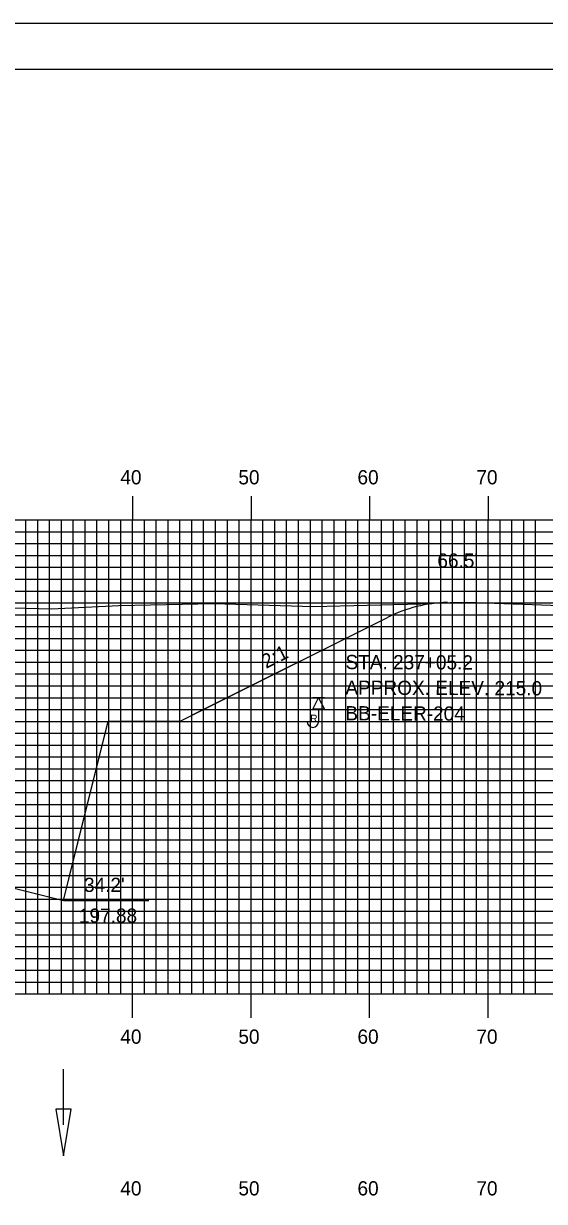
# Model space of a CAD drawing. Extents: x 1800749 to 1801092, y 442591 to 442811.
# Drawn here: x 1800945.4 to 1800989.3, y 442711.2 to 442810.5 of the extents above; entities that cross this region are included whole.
import ezdxf

# ---------------------------------------------------------------- set-up
doc = ezdxf.new("R2010")
doc.units = 0
for name, color, linetype in [('ANNOTATION', 7, 'Continuous'), ('BORDER', 7, 'Continuous'), ('BORING - REFUSAL', 7, 'Continuous'), ('D_Drainage_Ditch_Line', 7, 'Continuous'), ('D_Roadway_SlopeLines', 7, 'Continuous'), ('D_Text_Standard', 7, 'Continuous'), ('H_V ANNOTATION', 7, 'Continuous'), ('MAJOR', 7, 'Continuous'), ('MINOR', 7, 'Continuous'), ('PDRAIN', 7, 'Continuous'), ('PLOT BOUNDARY', 7, 'Continuous'), ('S_Roadway_Centerline', 7, 'Continuous')]:
    doc.layers.add(name, color=color, linetype=linetype)

msp = doc.modelspace()

# ---------------------------------------------------------------- linework, layer by layer
at = {"layer": 'ANNOTATION'}
for p, q in [((1800960.503, 442752.665), (1800976.044, 442760.436)), ((1800958.503, 442751.665), (1800960.503, 442752.665)), ((1800949.723, 442740.547), (1800952.503, 442751.665)), ((1800958.503, 442751.665), (1800952.503, 442751.665)), ((1800952.503, 442751.665), (1800958.503, 442751.665)), ((1800948.723, 442736.547), (1800949.723, 442740.547))]:
    msp.add_line(p, q, dxfattribs=at)
msp.add_arc((1800981.411, 442749.703), 12, 91.41331, 116.56505, dxfattribs=at)
at = {"layer": 'BORDER'}
msp.add_lwpolyline([(1800764.949, 442596.665), (1801084.949, 442596.665), (1801084.949, 442806.665), (1800764.949, 442806.665)], close=True, dxfattribs=at)
at = {"layer": 'BORING - REFUSAL'}
for p, q in [((1800970.729, 442753.665), (1800969.769, 442753.665)), ((1800970.249, 442752.706), (1800970.249, 442751.647))]:
    msp.add_line(p, q, dxfattribs=at)
msp.add_lwpolyline([(1800970.249, 442753.665), (1800970.729, 442752.706), (1800969.769, 442752.706)], close=True, dxfattribs=at)
msp.add_arc((1800969.764, 442751.647), 0.485, 180, 0, dxfattribs=at)
at = {"layer": 'D_Drainage_Ditch_Line'}
msp.add_line((1800948.724, 442717.626), (1800948.724, 442722.325), dxfattribs=at)
msp.add_lwpolyline([(1800949.38, 442718.939), (1800948.068, 442718.939), (1800948.724, 442715.002)], close=True, dxfattribs=at)
at = {"layer": 'D_Roadway_SlopeLines'}
for points in [[(1800948.723, 442736.547), (1800952.503, 442751.665), (1800958.503, 442751.665), (1800976.044, 442760.436)], [(1800934.549, 442740.091), (1800948.723, 442736.547)]]:
    msp.add_lwpolyline(points, dxfattribs=at)
at = {"layer": 'MAJOR'}
for p, q in [((1800954.549, 442770.669), (1800954.549, 442768.665)), ((1800964.549, 442770.669), (1800964.549, 442768.665)), ((1800974.549, 442770.669), (1800974.549, 442768.665)), ((1800984.549, 442770.669), (1800984.549, 442768.665)), ((1800774.549, 442768.665), (1801054.549, 442768.665)), ((1800774.549, 442768.665), (1801054.549, 442768.665)), ((1800954.549, 442728.665), (1800954.549, 442768.665)), ((1800964.549, 442728.665), (1800964.549, 442768.665)), ((1800974.549, 442728.665), (1800974.549, 442768.665)), ((1800984.549, 442728.665), (1800984.549, 442768.665)), ((1800774.549, 442763.665), (1801054.549, 442763.665)), ((1800774.549, 442758.665), (1801054.549, 442758.665)), ((1800774.549, 442753.665), (1801054.549, 442753.665)), ((1800774.549, 442748.665), (1801054.549, 442748.665)), ((1800774.549, 442743.665), (1801054.549, 442743.665)), ((1800774.549, 442738.665), (1801054.549, 442738.665)), ((1800774.549, 442733.665), (1801054.549, 442733.665)), ((1800774.549, 442728.665), (1801054.549, 442728.665)), ((1800774.549, 442728.665), (1801054.549, 442728.665)), ((1800954.549, 442726.661), (1800954.549, 442728.665)), ((1800964.549, 442726.661), (1800964.549, 442728.665)), ((1800974.549, 442726.661), (1800974.549, 442728.665)), ((1800984.549, 442726.661), (1800984.549, 442728.665))]:
    msp.add_line(p, q, dxfattribs=at)
at = {"layer": 'MINOR'}
for p, q in [((1800945.549, 442728.665), (1800945.549, 442768.665)), ((1800946.549, 442728.665), (1800946.549, 442768.665)), ((1800947.549, 442728.665), (1800947.549, 442768.665)), ((1800948.549, 442728.665), (1800948.549, 442768.665)), ((1800949.549, 442728.665), (1800949.549, 442768.665)), ((1800950.549, 442728.665), (1800950.549, 442768.665)), ((1800951.549, 442728.665), (1800951.549, 442768.665)), ((1800952.549, 442728.665), (1800952.549, 442768.665)), ((1800953.549, 442728.665), (1800953.549, 442768.665)), ((1800955.549, 442728.665), (1800955.549, 442768.665)), ((1800956.549, 442728.665), (1800956.549, 442768.665)), ((1800957.549, 442728.665), (1800957.549, 442768.665)), ((1800958.549, 442728.665), (1800958.549, 442768.665)), ((1800959.549, 442728.665), (1800959.549, 442768.665)), ((1800960.549, 442728.665), (1800960.549, 442768.665)), ((1800961.549, 442728.665), (1800961.549, 442768.665)), ((1800962.549, 442728.665), (1800962.549, 442768.665)), ((1800963.549, 442728.665), (1800963.549, 442768.665)), ((1800965.549, 442728.665), (1800965.549, 442768.665)), ((1800966.549, 442728.665), (1800966.549, 442768.665)), ((1800967.549, 442728.665), (1800967.549, 442768.665)), ((1800968.549, 442728.665), (1800968.549, 442768.665)), ((1800969.549, 442728.665), (1800969.549, 442768.665)), ((1800970.549, 442728.665), (1800970.549, 442768.665)), ((1800971.549, 442728.665), (1800971.549, 442768.665)), ((1800972.549, 442728.665), (1800972.549, 442768.665)), ((1800973.549, 442728.665), (1800973.549, 442768.665)), ((1800975.549, 442728.665), (1800975.549, 442768.665)), ((1800976.549, 442728.665), (1800976.549, 442768.665)), ((1800977.549, 442728.665), (1800977.549, 442768.665)), ((1800978.549, 442728.665), (1800978.549, 442768.665)), ((1800979.549, 442728.665), (1800979.549, 442768.665)), ((1800980.549, 442728.665), (1800980.549, 442768.665)), ((1800981.549, 442728.665), (1800981.549, 442768.665)), ((1800982.549, 442728.665), (1800982.549, 442768.665)), ((1800983.549, 442728.665), (1800983.549, 442768.665)), ((1800985.549, 442728.665), (1800985.549, 442768.665)), ((1800986.549, 442728.665), (1800986.549, 442768.665)), ((1800987.549, 442728.665), (1800987.549, 442768.665)), ((1800988.549, 442728.665), (1800988.549, 442768.665)), ((1800774.549, 442767.665), (1801054.549, 442767.665)), ((1800774.549, 442766.665), (1801054.549, 442766.665)), ((1800774.549, 442765.665), (1801054.549, 442765.665)), ((1800774.549, 442764.665), (1801054.549, 442764.665)), ((1800774.549, 442762.665), (1801054.549, 442762.665)), ((1800774.549, 442761.665), (1801054.549, 442761.665)), ((1800774.549, 442760.665), (1801054.549, 442760.665)), ((1800774.549, 442759.665), (1801054.549, 442759.665)), ((1800774.549, 442757.665), (1801054.549, 442757.665)), ((1800774.549, 442756.665), (1801054.549, 442756.665)), ((1800774.549, 442755.665), (1801054.549, 442755.665)), ((1800774.549, 442754.665), (1801054.549, 442754.665)), ((1800774.549, 442752.665), (1801054.549, 442752.665)), ((1800774.549, 442751.665), (1801054.549, 442751.665)), ((1800774.549, 442750.665), (1801054.549, 442750.665)), ((1800774.549, 442749.665), (1801054.549, 442749.665)), ((1800774.549, 442747.665), (1801054.549, 442747.665)), ((1800774.549, 442746.665), (1801054.549, 442746.665)), ((1800774.549, 442745.665), (1801054.549, 442745.665)), ((1800774.549, 442744.665), (1801054.549, 442744.665)), ((1800774.549, 442742.665), (1801054.549, 442742.665)), ((1800774.549, 442741.665), (1801054.549, 442741.665)), ((1800774.549, 442740.665), (1801054.549, 442740.665)), ((1800774.549, 442739.665), (1801054.549, 442739.665)), ((1800774.549, 442737.665), (1801054.549, 442737.665)), ((1800774.549, 442736.665), (1801054.549, 442736.665)), ((1800774.549, 442735.665), (1801054.549, 442735.665)), ((1800774.549, 442734.665), (1801054.549, 442734.665)), ((1800774.549, 442732.665), (1801054.549, 442732.665)), ((1800774.549, 442731.665), (1801054.549, 442731.665)), ((1800774.549, 442730.665), (1801054.549, 442730.665)), ((1800774.549, 442729.665), (1801054.549, 442729.665))]:
    msp.add_line(p, q, dxfattribs=at)
at = {"layer": 'PDRAIN'}
msp.add_line((1800948.723, 442736.547), (1800955.917, 442736.547), dxfattribs=at)
at = {"layer": 'PLOT BOUNDARY'}
msp.add_lwpolyline([(1800748.763, 442590.547), (1801088.763, 442590.547), (1801088.763, 442810.547), (1800748.763, 442810.547)], close=True, dxfattribs=at)
at = {"layer": 'S_Roadway_Centerline'}
msp.add_lwpolyline([(1800866.1, 442761.904), (1800875.807, 442761.911), (1800883.239, 442761.453), (1800885.214, 442761.45), (1800887.306, 442761.449), (1800894.628, 442761.623), (1800904.587, 442761.45), (1800913.116, 442761.584), (1800929.195, 442761.256), (1800930.25, 442761.216), (1800931.784, 442761.218), (1800942.325, 442761.297), (1800947.724, 442761.167), (1800953.393, 442761.434), (1800961.402, 442761.623), (1800969.813, 442761.349), (1800978.864, 442761.572), (1800980.005, 442761.672), (1800982.683, 442761.738), (1801004.152, 442760.964)], dxfattribs=at)

# ---------------------------------------------------------------- texts
at = {"layer": 'ANNOTATION'}
msp.add_text('2:1', height=1.2, rotation=26.56505, dxfattribs=at).set_placement((1800965.809, 442756.089))
for s, p in [("34.2'", (1800950.456, 442737.273)), ('197.88', (1800950.028, 442734.673))]:
    msp.add_text(s, height=1.2, dxfattribs=at).set_placement(p)
at = {"layer": 'BORING - REFUSAL'}
for s, p in [('STA. 237+05.2', (1800972.51, 442756.075)), ('APPROX. ELEV. 215.0', (1800972.503, 442753.915)), ('BB-ELER-204', (1800972.496, 442751.755))]:
    msp.add_text(s, height=1.2, rotation=359.81416, dxfattribs=at).set_placement(p)
msp.add_text('R', height=0.64, dxfattribs=at).set_placement((1800969.54, 442751.591))
at = {"layer": 'D_Text_Standard'}
msp.add_text("66.5'", height=1.2, dxfattribs=at).set_placement((1800980.262, 442764.641))
at = {"layer": 'H_V ANNOTATION'}
for s, p in [('40', (1800953.522, 442771.665)), ('50', (1800963.479, 442771.665)), ('60', (1800973.522, 442771.665)), ('70', (1800983.553, 442771.665)), ('40', (1800953.522, 442724.465)), ('50', (1800963.479, 442724.465)), ('60', (1800973.522, 442724.465)), ('70', (1800983.553, 442724.465)), ('40', (1800953.522, 442711.665)), ('50', (1800963.479, 442711.665)), ('60', (1800973.522, 442711.665)), ('70', (1800983.553, 442711.665))]:
    msp.add_text(s, height=1.2, dxfattribs=at).set_placement(p)

doc.saveas('drawing.dxf')
